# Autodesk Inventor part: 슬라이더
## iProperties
Company: 한국ATC센터
Created: 2014-08
Part Number: 슬라이더
Document SubType Name: Modeling
Designer: KYOUNG IL JANG
Density: 7.86 g/cm^3
Material: 강, 연강
Mass: 107.623 g
Surface Area: 43.9337 cm^2
Volume: 13.6925 cm^3
Author: KYOUNG IL JANG
